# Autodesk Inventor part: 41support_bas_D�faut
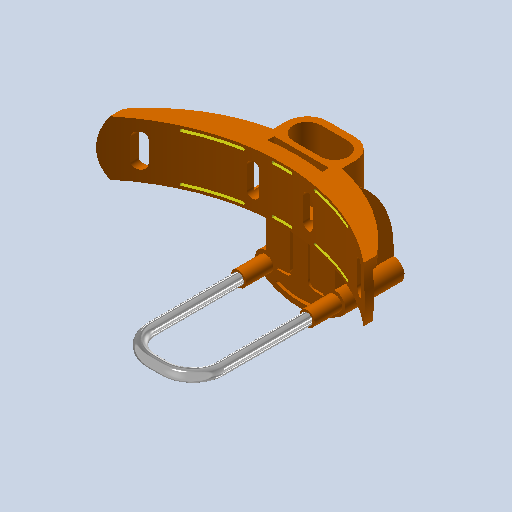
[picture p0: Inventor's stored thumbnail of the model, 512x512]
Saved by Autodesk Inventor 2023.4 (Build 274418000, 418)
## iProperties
Created: 2011-01
Part Number: 41support_bas_D�faut
Document SubType Name: Modeling
Designer: eric
Density: 1 g/cm^3
Mass: 167.686 g
Surface Area: 645.645 cm^2
Volume: 167.686 cm^3
Material: Générique
Appearance: Lisse - Gris moyen
Author: eric
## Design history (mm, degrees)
feature "Base1"
node "Corps solides"
node "Corps surfaciques"
node "Solide1"
